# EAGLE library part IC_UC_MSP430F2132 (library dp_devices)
16-bit Ultra-Low-Power Microcontroller, 8kB Flash, 512B RAM, 10 bit ADC, 1 USCI
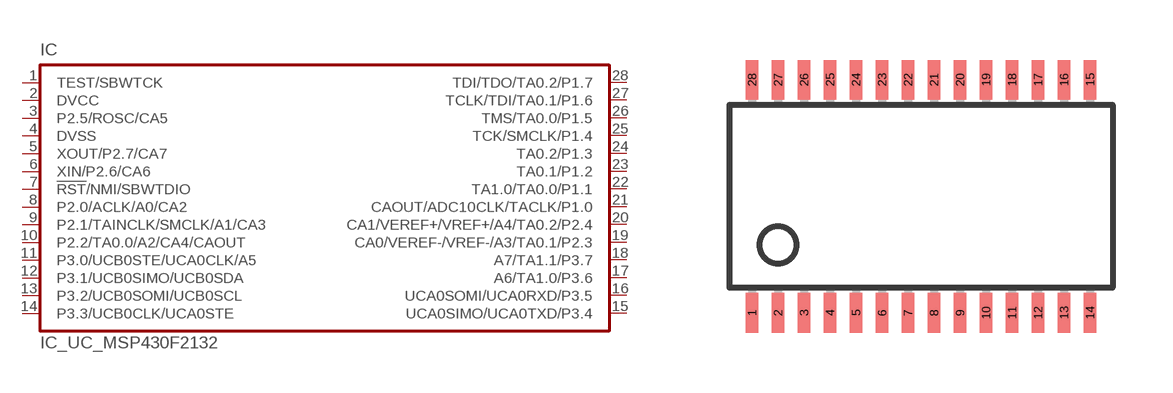
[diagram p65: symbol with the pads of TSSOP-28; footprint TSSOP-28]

Designator prefix IC

## IC_UC_MSP430F2132  [TSSOP-28]
1  TEST/SBWTCK  in
2  DVCC  pwr
3  P2.5/ROSC/CA5
4  DVSS  pwr
5  XOUT/P2.7/CA7
6  XIN/P2.6/CA6
7  !RST!/NMI/SBWTDIO  in
8  P2.0/ACLK/A0/CA2
9  P2.1/TAINCLK/SMCLK/A1/CA3
10  P2.2/TA0.0/A2/CA4/CAOUT
11  P3.0/UCB0STE/UCA0CLK/A5
12  P3.1/UCB0SIMO/UCB0SDA
13  P3.2/UCB0SOMI/UCB0SCL
14  P3.3/UCB0CLK/UCA0STE
15  UCA0SIMO/UCA0TXD/P3.4
16  UCA0SOMI/UCA0RXD/P3.5
17  A6/TA1.0/P3.6
18  A7/TA1.1/P3.7
19  CA0/VEREF-/VREF-/A3/TA0.1/P2.3  pwr
20  CA1/VEREF+/VREF+/A4/TA0.2/P2.4  pwr
21  CAOUT/ADC10CLK/TACLK/P1.0
22  TA1.0/TA0.0/P1.1
23  TA0.1/P1.2
24  TA0.2/P1.3
25  TCK/SMCLK/P1.4
26  TMS/TA0.0/P1.5
27  TCLK/TDI/TA0.1/P1.6
28  TDI/TDO/TA0.2/P1.7

## Footprint TSSOP-28 (pad centres in mm)
Thin Shrink Small Outline Plastic 28 (TSSOP28)
smd 0.305 x 0.991: 1 -4.225,-2.918; 2 -3.575,-2.918; 3 -2.925,-2.918; 4 -2.275,-2.918; 5 -1.625,-2.918; 6 -0.975,-2.918; 7 -0.325,-2.918; 8 0.325,-2.918; 9 0.975,-2.918; 10 1.625,-2.918; 11 2.275,-2.918; 12 2.925,-2.918; 13 3.575,-2.918; 14 4.225,-2.918; 15 4.225,2.918; 16 3.575,2.918; 17 2.925,2.918; 18 2.275,2.918; 19 1.625,2.918; 20 0.975,2.918; 21 0.325,2.918; 22 -0.325,2.918; 23 -0.975,2.918; 24 -1.625,2.918; 25 -2.275,2.918; 26 -2.925,2.918; 27 -3.575,2.918; 28 -4.225,2.918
